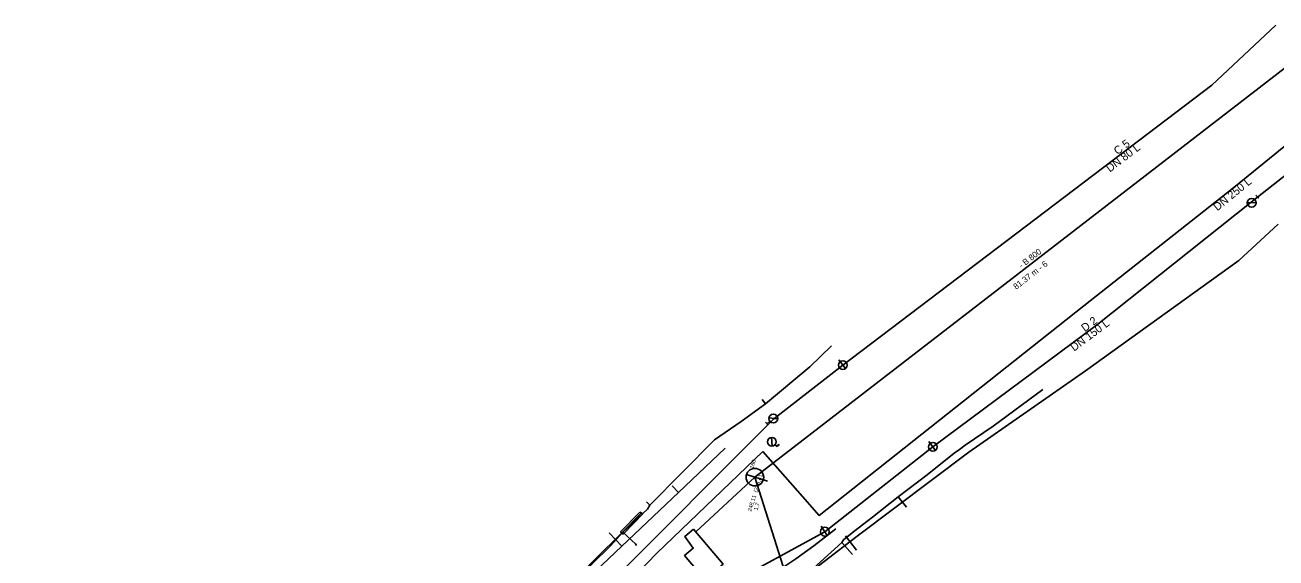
# Model space of a CAD drawing. Extents: x -600636 to -600148, y -1203980 to -1203569.
# Drawn here: x -600456.1 to -600313.9, y -1203630.1 to -1203569.5 of the extents above; entities that cross this region are included whole.
import ezdxf

# ---------------------------------------------------------------- set-up
doc = ezdxf.new("R2010")
doc.units = 0
for name, color, linetype in [('Cetin zam průběh', 7, 'Continuous'), ('EON podzemní NN', 7, 'Continuous'), ('GasNet NTL', 7, 'Continuous'), ('Implicitní', 7, 'Continuous'), ('VaK Břeclav_kanalizace', 7, 'Continuous'), ('VaK Břeclav_kanalizace_popis', 7, 'Continuous'), ('Vak Břeclav_vodovod', 7, 'Continuous'), ('Vak Břeclav_vodovod_popis', 7, 'Continuous')]:
    doc.layers.add(name, color=color, linetype=linetype)

# ---------------------------------------------------------------- blocks, each defined once
blk = doc.blocks.new('MoSymbol 2')
at = {"layer": 'Implicitní'}
blk.add_line((0, 0.0005), (0, -0.00075), dxfattribs=at)
blk.add_circle((0, 0), 0.0005, dxfattribs=at)
blk = doc.blocks.new('MoSymbol 3')
at = {"layer": 'Implicitní'}
for p, q in [((-0.000365, -0.000365), (0.000365, 0.000365)), ((-0.000225, 0.00095), (0.000225, 0.00095)), ((0, 0.00095), (0, 0.0005))]:
    blk.add_line(p, q, dxfattribs=at)
blk.add_circle((0, 0), 0.0005, dxfattribs=at)
blk = doc.blocks.new('MoSymbol 4')
at = {"layer": 'Implicitní'}
for p, q in [((-0.000365, -0.000365), (0.000365, 0.000365)), ((0.0003, -0.0008), (0.0002, -0.00085))]:
    blk.add_line(p, q, dxfattribs=at)
blk.add_lwpolyline([(0, -0.0005), (0, -0.0008), (0.0003, -0.0008), (0.0002, -0.00075)], dxfattribs=at)
blk.add_circle((0, 0), 0.0005, dxfattribs=at)

msp = doc.modelspace()

# ---------------------------------------------------------------- linework, layer by layer
at = {"layer": 'Cetin zam průběh'}
for points in [[(-600403.75, -1203662.4), (-600400.59, -1203659.29), (-600391.04, -1203649.83), (-600378.25, -1203637.79), (-600376.97, -1203637.47), (-600375.66, -1203637.95), (-600375.36, -1203637.74), (-600369.01, -1203633.38), (-600361.52, -1203627.61), (-600348.82, -1203618.06), (-600335.53, -1203608.82), (-600318.11, -1203596.27), (-600313.64, -1203592.14)], [(-600371.93, -1203612.56), (-600366.88, -1203608.36), (-600364.43, -1203605.96)], [(-600356.85, -1203623.13), (-600353.54, -1203620.63), (-600350.46, -1203618.17), (-600349.88, -1203617.76), (-600349.23, -1203617.28), (-600346.05, -1203615.09), (-600340.39, -1203610.92)], [(-600385.06, -1203624.09), (-600377.73, -1203616.65), (-600374.7, -1203614.56), (-600371.93, -1203612.56)], [(-600371.93, -1203612.56), (-600372.32, -1203612.09)], [(-600377.73, -1203616.65), (-600374.7, -1203614.56)], [(-600353.54, -1203620.63), (-600350.46, -1203618.17)], [(-600388.16, -1203627.18), (-600385.34, -1203624.55), (-600385.06, -1203624.09)], [(-600385.06, -1203624.09), (-600385.47, -1203623.7)], [(-600359.74, -1203625.45), (-600356.85, -1203623.13)], [(-600356.85, -1203623.13), (-600355.91, -1203624.31)], [(-600388.16, -1203627.18), (-600385.34, -1203624.55)], [(-600363.25, -1203628.32), (-600363.07, -1203628.05), (-600361.87, -1203627.08), (-600359.74, -1203625.45)], [(-600389.61, -1203628.78), (-600389.52, -1203628.69), (-600388.16, -1203627.18)], [(-600389.52, -1203628.69), (-600388.16, -1203627.18)], [(-600388.16, -1203627.18), (-600386.71, -1203628.5)], [(-600388.16, -1203627.18), (-600386.71, -1203628.5), (-600386.58, -1203628.67)], [(-600368.09, -1203632.74), (-600363.25, -1203628.32)], [(-600363.25, -1203628.32), (-600362.03, -1203629.72)], [(-600363.07, -1203628.05), (-600361.87, -1203627.08)], [(-600396.73, -1203635.32), (-600394.24, -1203633.29), (-600389.88, -1203629.05)], [(-600389.88, -1203629.05), (-600389.61, -1203628.78)]]:
    msp.add_lwpolyline(points, dxfattribs=at)
at = {"layer": 'EON podzemní NN'}
msp.add_lwpolyline([(-600394.24, -1203633.14), (-600388.26, -1203627.25), (-600386.06, -1203624.99)], dxfattribs=at)
msp.add_lwpolyline([(-600386.23, -1203624.89), (-600385.88, -1203625.09), (-600388.12, -1203627.38), (-600388.4, -1203627.11)], close=True, dxfattribs=at)
at = {"layer": 'GasNet NTL'}
for points in [[(-600376.52, -1203617.62), (-600381.81, -1203622.65), (-600388.25, -1203628.77), (-600399.65, -1203639.6), (-600410.04, -1203649.48), (-600410.35, -1203649.77), (-600417.47, -1203657.21), (-600420.27, -1203660.14), (-600432.74, -1203673.17), (-600439.94, -1203680.7), (-600445.87, -1203686.85), (-600458.57, -1203700.01), (-600466.75, -1203707.26), (-600469.55, -1203709.74), (-600472.59, -1203712.26), (-600475.67, -1203714.29), (-600481.14, -1203718.36), (-600486.68, -1203722.48)], [(-600382.53, -1203621.89), (-600381.81, -1203622.65)], [(-600363.91, -1203626.79), (-600366.43, -1203628.72), (-600368.49, -1203630.18), (-600377.69, -1203636.35), (-600377.83, -1203636.45), (-600379.12, -1203637.4), (-600390.52, -1203649.08), (-600393.75, -1203652.39), (-600407.12, -1203666.06), (-600410.69, -1203669.71), (-600416.55, -1203675.06), (-600425.93, -1203683.63), (-600443.22, -1203700.03), (-600443.4, -1203700.21), (-600447.92, -1203704.5), (-600448.05, -1203704.62)], [(-600389.69, -1203627.25), (-600388.25, -1203628.77)], [(-600362.82, -1203627.58), (-600361.57, -1203629.22)]]:
    msp.add_lwpolyline(points, dxfattribs=at)
at = {"layer": 'VaK Břeclav_kanalizace'}
for p, q in [((-600309.64, -1203571.84), (-600373.13, -1203620.91)), ((-600373.13, -1203620.91), (-600379.85, -1203627.13)), ((-600373.13, -1203620.91), (-600367.91, -1203637.36))]:
    msp.add_line(p, q, dxfattribs=at)
msp.add_lwpolyline([(-600380.11, -1203626.82), (-600381.1, -1203627.66), (-600380.13, -1203628.99), (-600381.12, -1203629.83), (-600378.83, -1203632.54), (-600376.75, -1203630.79)], close=True, dxfattribs=at)
at = {"layer": 'Vak Břeclav_vodovod'}
for p, q in [((-600316.71, -1203589.64), (-600300.57, -1203576.9)), ((-600363.13, -1203608.16), (-600370.99, -1203614.29)), ((-600370.99, -1203614.29), (-600423.62, -1203667.02)), ((-600365.17, -1203627.11), (-600352.89, -1203617.46)), ((-600377.98, -1203634.08), (-600365.17, -1203627.11))]:
    msp.add_line(p, q, dxfattribs=at)
for points in [[(-600313.89, -1203569.48), (-600321.18, -1203576.33), (-600332.51, -1203584.93), (-600363.13, -1203608.16)], [(-600303.26, -1203575.4), (-600318.68, -1203587.96), (-600335.72, -1203601.41), (-600365.84, -1203625.25), (-600367.7, -1203623.11), (-600372.22, -1203617.99)], [(-600352.89, -1203617.46), (-600334.15, -1203603.51), (-600316.71, -1203589.64)], [(-600372.22, -1203617.99), (-600384.28, -1203629.56), (-600410.01, -1203656.15), (-600451.09, -1203698.02), (-600454.25, -1203701.01)]]:
    msp.add_lwpolyline(points, dxfattribs=at)

# ---------------------------------------------------------------- block references
at = {"layer": 'VaK Břeclav_kanalizace', "xscale": 1999.7500312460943, "yscale": 1999.750031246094, "rotation": 72.64048260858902}
msp.add_blockref('MoSymbol 2', (-600373.13, -1203620.91), dxfattribs=at)
at = {"layer": 'Vak Břeclav_vodovod'}
for name, p, xscale, yscale, rotation in [('MoSymbol 3', (-600316.65, -1203589.7), 999.875015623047, 999.8750156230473, -42.80392229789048), ('MoSymbol 2', (-600363.13, -1203608.16), 999.875015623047, 999.875015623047, -142.43906434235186), ('MoSymbol 3', (-600371.03, -1203614.23), 999.8750156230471, 999.8750156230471, 128.5630116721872), ('MoSymbol 4', (-600371.2, -1203616.88), 999.8750156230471, 999.8750156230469, 47.66988975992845), ('MoSymbol 2', (-600352.89, -1203617.46), 999.8750156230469, 999.8750156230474, -142.5887421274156), ('MoSymbol 2', (-600365.17, -1203627.11), 999.8750156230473, 999.875015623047, -146.63737693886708)]:
    msp.add_blockref(name, p, dxfattribs=dict(at, xscale=xscale, yscale=yscale, rotation=rotation))

# ---------------------------------------------------------------- texts
at = {"layer": 'VaK Břeclav_kanalizace_popis'}
for s, height, rotation, p in [('- B 800', 0.682, 37.6984, (-600342.81, -1203597.19)), ('81.37 m - 6', 0.6824, 37.6984, (-600343.42, -1203599.61)), ('160', 0.455, 72.6405, (-600373.31, -1203619.99)), ('248,11  (246,41)', 0.4549, 72.6405, (-600373.54, -1203624.85)), ('1.7', 0.455, 72.6405, (-600372.84, -1203624.73))]:
    msp.add_text(s, height=height, rotation=rotation, dxfattribs=at).set_placement(p)
at = {"layer": 'Vak Břeclav_vodovod_popis'}
for s, rotation, p in [('C 5', 37.1988, (-600331.9, -1203584.29)), ('DN 80 L', 37.1988, (-600332.77, -1203586.27)), ('DN 250 L', 39.1629, (-600320.55, -1203590.67)), ('D 2', 36.656, (-600335.61, -1203604.42)), ('DN 150 L', 36.656, (-600336.84, -1203606.64))]:
    msp.add_text(s, height=0.91, rotation=rotation, dxfattribs=at).set_placement(p)

doc.saveas('drawing.dxf')
